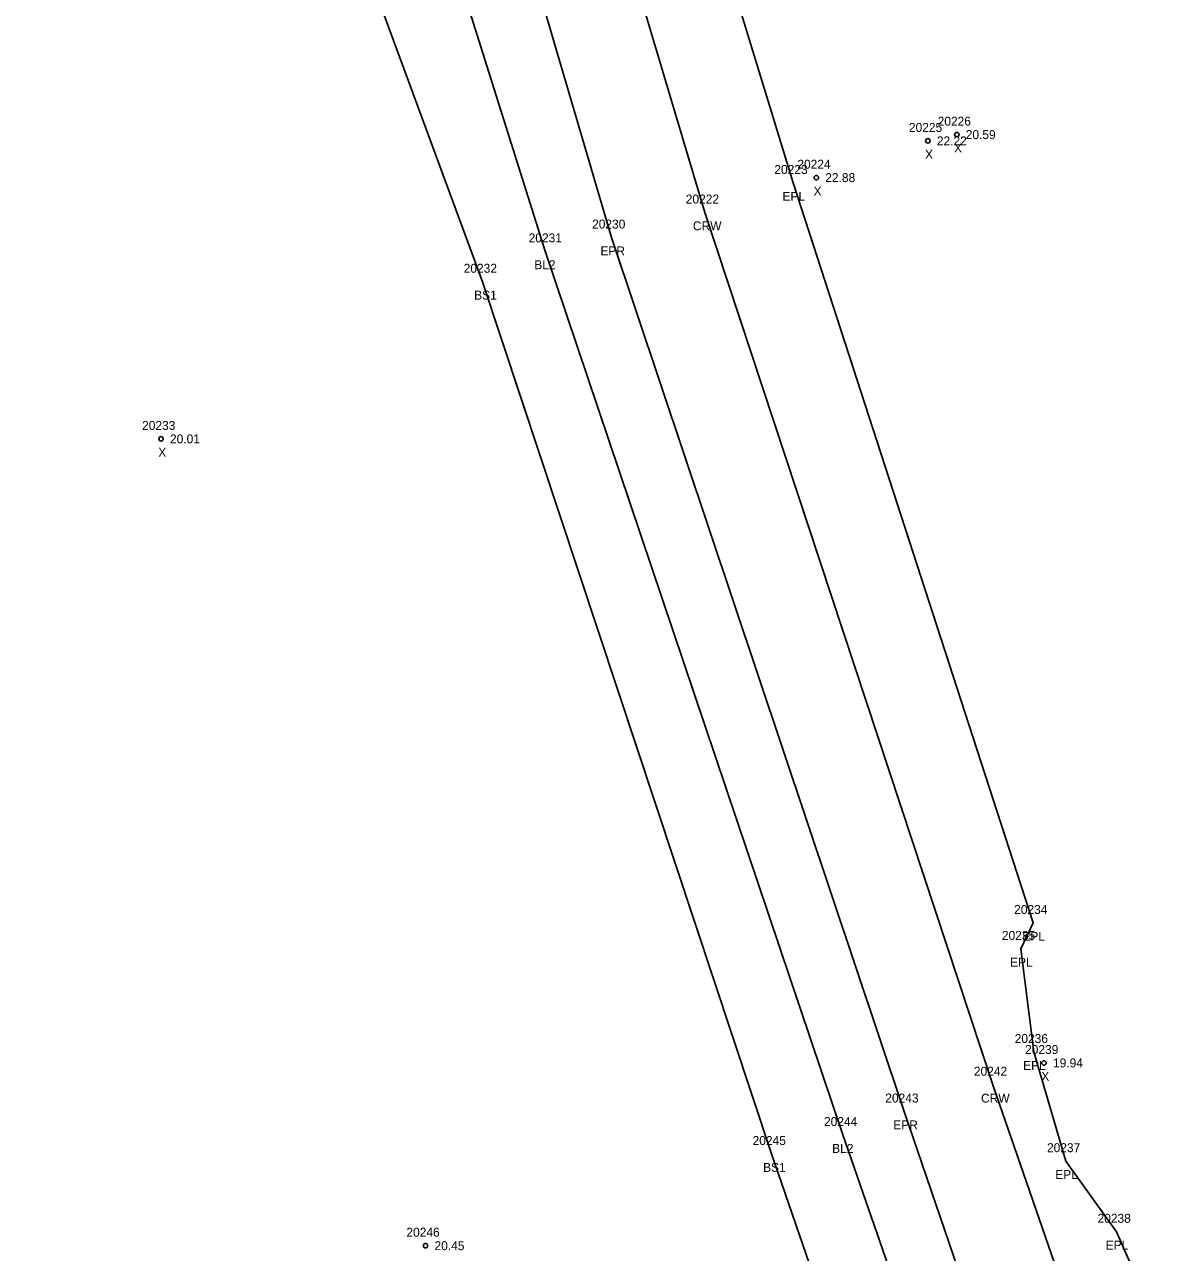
# Model space of a CAD drawing. Extents: x 2432729 to 2433340, y 684958 to 688103.
# Drawn here: x 2432899 to 2433027.4, y 686750.6 to 686887.8 of the extents above; entities that cross this region are included whole.
import ezdxf

# ---------------------------------------------------------------- set-up
doc = ezdxf.new("R2010")
doc.units = 0
for name, color, linetype in [('RD_DTM_BkLn1', 7, 'Continuous'), ('RD_DTM_BkLn2', 7, 'Continuous'), ('RD_EX_Road', 7, 'Continuous'), ('RD_EX_Road_txCode', 7, 'Continuous'), ('RD_Sketch8', 7, 'Continuous'), ('RD_SMD_Locator', 7, 'Continuous'), ('RD_SMD_Misc', 7, 'Continuous')]:
    doc.layers.add(name, color=color, linetype=linetype)

msp = doc.modelspace()

# ---------------------------------------------------------------- linework, layer by layer
at = {"layer": 'RD_DTM_BkLn1'}
for points in [[(2432926.02, 687213.66), (2432924.35, 687158.94), (2432925.68, 687108.84), (2432939.7, 687000.92), (2432956.93, 686927.39), (2432975, 686866.8), (2433007.19, 686769.33), (2433041.66, 686669.67), (2433075.97, 686569.51), (2433108.49, 686474.01), (2433123.82, 686426.48), (2433137.99, 686374.7), (2433148.76, 686320.1), (2433154.8, 686269.16), (2433155.78, 686212.93), (2433152.37, 686164.52), (2433145.67, 686113.9), (2433140.38, 686078.83)], [(2432898.98, 687049.37), (2432906.9, 687044.55), (2432919.33, 686997.25), (2432938.84, 686920.72), (2432957.15, 686862.46), (2432990.45, 686763.71), (2433024.84, 686664.51), (2433058.68, 686562.8), (2433090.41, 686467.11), (2433107.21, 686420.87), (2433120.26, 686369.86), (2433132.05, 686313.5), (2433136.59, 686267.4), (2433133.92, 686213.17), (2433133.74, 686165.58), (2433125.69, 686115.89), (2433123.08, 686088.41), (2433128.09, 686081.14)]]:
    msp.add_lwpolyline(points, dxfattribs=at)
at = {"layer": 'RD_DTM_BkLn2'}
msp.add_lwpolyline([(2432916.74, 686973.9), (2432925.37, 686926.35), (2432950.18, 686859.06), (2432982.46, 686761.59), (2433017.67, 686659.38), (2433053.8, 686561.16), (2433080.54, 686460.75), (2433098.39, 686424.64), (2433113.62, 686368.79), (2433123.31, 686312.63), (2433128.29, 686266.56), (2433126.49, 686214.47), (2433123.88, 686164.31), (2433114.46, 686111.82), (2433110.48, 686084.68), (2433120.95, 686072.12)], dxfattribs=at)
at = {"layer": 'RD_EX_Road'}
for points in [[(2432915.64, 687215.4), (2432913.86, 687159.12), (2432915.08, 687107.55), (2432919.97, 687053.4), (2432928.7, 686998.89), (2432946.77, 686924.59), (2432964.57, 686864), (2432997.3, 686766.34), (2433031.44, 686666.38), (2433066.06, 686565.78), (2433098.73, 686469.74), (2433113.88, 686422.91), (2433127.93, 686372.14), (2433139.1, 686314.76), (2433144.47, 686268.02), (2433145.44, 686213), (2433142.32, 686164.92), (2433135.44, 686115.75), (2433128.09, 686081.14)], [(2432937.12, 687213.43), (2432935.51, 687158.7), (2432936.54, 687110.38), (2432944.97, 687033.04), (2432950.24, 687002.26), (2432966.49, 686930.23), (2432984.9, 686870.1), (2433011.7, 686787.41), (2433010.33, 686784.51), (2433011.78, 686772.99), (2433015.37, 686760.79), (2433021.02, 686752.9), (2433031.88, 686728.09), (2433052.76, 686670.56), (2433070.23, 686619.38), (2433072.02, 686607.31)]]:
    msp.add_lwpolyline(points, dxfattribs=at)
at = {"layer": 'RD_SMD_Locator'}
for centre, radius in [((2433003.17, 686875.5), 0.25), ((2432999.94, 686874.8), 0.25), ((2432984.9, 686870.1), 0.001), ((2432987.47, 686870.69), 0.25), ((2432975, 686866.8), 0.001), ((2432964.57, 686864), 0.001), ((2432957.15, 686862.46), 0.001), ((2432950.18, 686859.06), 0.001), ((2432914.24, 686841.5), 0.25), ((2433011.7, 686787.41), 0.001), ((2433010.33, 686784.51), 0.001), ((2433011.78, 686772.99), 0.001), ((2433012.92, 686771.76), 0.25), ((2433007.19, 686769.33), 0.001), ((2432997.3, 686766.34), 0.001), ((2432990.45, 686763.71), 0.001), ((2432982.46, 686761.59), 0.001), ((2433015.37, 686760.79), 0.001), ((2433021.02, 686752.9), 0.001), ((2432943.8, 686751.34), 0.25)]:
    msp.add_circle(centre, radius, dxfattribs=at)

# ---------------------------------------------------------------- texts
at = {"layer": 'RD_EX_Road_txCode'}
for s, p in [('20223', (2432982.78, 686871.1)), ('EPL', (2432983.69, 686868.1)), ('20230', (2432962.41, 686865)), ('EPR', (2432963.34, 686862)), ('20234', (2433009.58, 686788.41)), ('20235', (2433008.21, 686785.51)), ('EPL', (2433010.5, 686785.41)), ('EPL', (2433009.12, 686782.51)), ('20236', (2433009.64, 686773.99)), ('EPL', (2433010.58, 686770.99)), ('20243', (2432995.18, 686767.34)), ('EPR', (2432996.07, 686764.34)), ('20237', (2433013.25, 686761.79)), ('EPL', (2433014.17, 686758.79)), ('20238', (2433018.9, 686753.9)), ('EPL', (2433019.81, 686750.9))]:
    msp.add_text(s, height=1, dxfattribs=at).set_placement(p)
at = {"layer": 'RD_Sketch8'}
for s, p in [('20226', (2433001.03, 686876.5)), ('20225', (2432997.82, 686875.8)), ('20.59', (2433004.17, 686875)), ('22.22', (2433000.94, 686874.3)), ('X', (2433002.86, 686873.5)), ('X', (2432999.62, 686872.8)), ('20224', (2432985.35, 686871.69)), ('22.88', (2432988.47, 686870.19)), ('X', (2432987.16, 686868.69)), ('20233', (2432912.12, 686842.5)), ('20.01', (2432915.24, 686841)), ('X', (2432913.93, 686839.5)), ('20239', (2433010.8, 686772.76)), ('19.94', (2433013.92, 686771.26)), ('X', (2433012.61, 686769.76)), ('20246', (2432941.66, 686752.34)), ('20.45', (2432944.8, 686750.84))]:
    msp.add_text(s, height=1, dxfattribs=at).set_placement(p)
at = {"layer": 'RD_SMD_Misc'}
for s, p in [('20222', (2432972.88, 686867.8)), ('CRW', (2432973.68, 686864.8)), ('20231', (2432955.32, 686863.46)), ('20232', (2432948.06, 686860.06)), ('BL2', (2432955.95, 686860.46)), ('BS1', (2432949.23, 686857.06)), ('20242', (2433005.08, 686770.33)), ('CRW', (2433005.88, 686767.33)), ('20244', (2432988.33, 686764.71)), ('20245', (2432980.35, 686762.59)), ('BL2', (2432989.24, 686761.71)), ('BS1', (2432981.52, 686759.59))]:
    msp.add_text(s, height=1, dxfattribs=at).set_placement(p)

doc.saveas('drawing.dxf')
